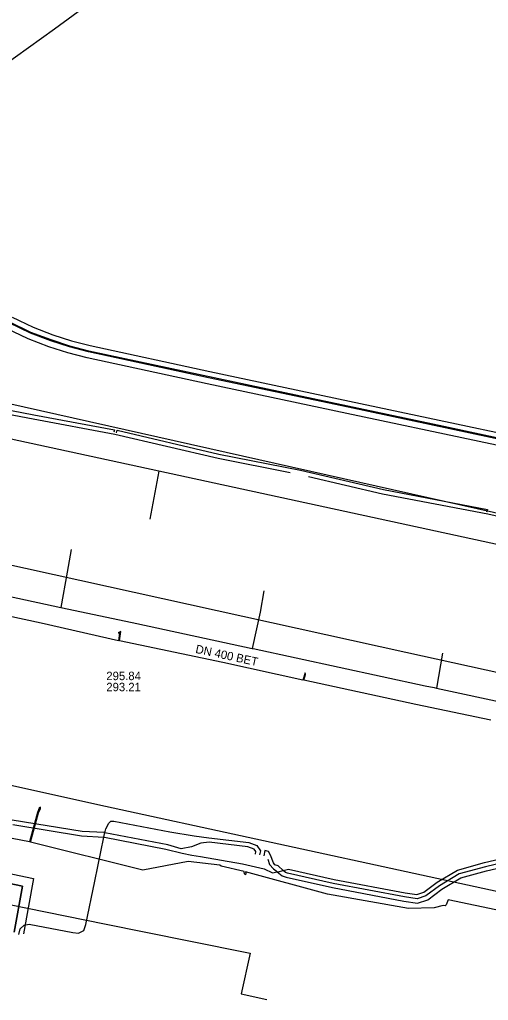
# Model space of a CAD drawing. Extents: x -598233 to -596890, y -1157848 to -1156431.
# Drawn here: x -597143.3 to -597098.9, y -1156713.1 to -1156620.3 of the extents above; entities that cross this region are included whole.
import ezdxf

# ---------------------------------------------------------------- set-up
doc = ezdxf.new("R2010")
doc.units = 0
for name, color, linetype in [('Vrstva 12', 7, 'Continuous'), ('Vrstva 13', 7, 'Continuous'), ('Vrstva 19', 7, 'Continuous'), ('Vrstva 25', 7, 'Continuous'), ('Vrstva 26', 7, 'Continuous'), ('Vrstva 37', 7, 'Continuous'), ('Vrstva 38', 7, 'Continuous'), ('Vrstva 42', 7, 'Continuous'), ('Vrstva 55', 7, 'Continuous'), ('Vrstva 9', 7, 'Continuous')]:
    doc.layers.add(name, color=color, linetype=linetype)

msp = doc.modelspace()

# ---------------------------------------------------------------- linework, layer by layer
at = {"layer": 'Vrstva 12'}
for points in [[(-597002.27, -1156687.69), (-597020.83, -1156683.69), (-597091.98, -1156668.39), (-597150.87, -1156655.17)], [(-597149.84, -1156702.93), (-597135.23, -1156705.9), (-597127.25, -1156707.5)], [(-597127.25, -1156707.5), (-597121.47, -1156708.66), (-597122.31, -1156712.53), (-597119.87, -1156713.06)]]:
    msp.add_lwpolyline(points, dxfattribs=at)
at = {"layer": 'Vrstva 13'}
for points in [[(-597144.89, -1156624.69), (-597139.98, -1156621.16), (-597135.15, -1156617.58)], [(-597084.22, -1156685.17), (-597106.726, -1156680.198), (-597165.716, -1156667.167), (-597175.517, -1156665.001)]]:
    msp.add_lwpolyline(points, dxfattribs=at)
at = {"layer": 'Vrstva 19'}
msp.add_lwpolyline([(-597153.74, -1156690.63), (-597135.86, -1156694.59), (-597088.849, -1156704.811), (-597082.78, -1156706.13), (-597053.385, -1156713.142)], dxfattribs=at)
at = {"layer": 'Vrstva 25'}
msp.add_lwpolyline([(-597087.165, -1156662.298), (-597112.173, -1156656.978), (-597125.389, -1156654.183), (-597136.739, -1156651.732), (-597138.536, -1156651.265), (-597140.312, -1156650.68), (-597142.231, -1156649.963), (-597144.243, -1156648.998)], dxfattribs=at)
at = {"layer": 'Vrstva 26'}
for points in [[(-597143.971, -1156648.463), (-597141.996, -1156649.41), (-597140.113, -1156650.114), (-597138.367, -1156650.689), (-597136.601, -1156651.148), (-597125.264, -1156653.596), (-597112.049, -1156656.391), (-597087.039, -1156661.711)], [(-597087.29, -1156662.885), (-597112.298, -1156657.564), (-597125.515, -1156654.769), (-597136.878, -1156652.315), (-597138.706, -1156651.841), (-597140.511, -1156651.246), (-597142.466, -1156650.515), (-597144.515, -1156649.533)]]:
    msp.add_lwpolyline(points, dxfattribs=at)
at = {"layer": 'Vrstva 37'}
for p, q in [((-597130.1, -1156663.037), (-597130.94, -1156667.563)), ((-597089.088, -1156671.932), (-597130.1, -1156663.037))]:
    msp.add_line(p, q, dxfattribs=at)
for points in [[(-597130.1, -1156663.037), (-597160.394, -1156656.466), (-597160.772, -1156658.504), (-597163.161, -1156657.986)], [(-597179.006, -1156694.768), (-597142.983, -1156702.318), (-597143.773, -1156706.674)], [(-597143.773, -1156706.674), (-597142.983, -1156702.318), (-597179.003, -1156694.755)]]:
    msp.add_lwpolyline(points, dxfattribs=at)
at = {"layer": 'Vrstva 38'}
msp.add_lwpolyline([(-597177.936, -1156694.073), (-597141.941, -1156701.617), (-597142.887, -1156706.835)], dxfattribs=at)
at = {"layer": 'Vrstva 42'}
for points in [[(-597096.4, -1156660.25), (-597103.15, -1156658.82), (-597112.23, -1156656.88), (-597121.46, -1156654.93), (-597130.78, -1156652.94), (-597136.72, -1156651.66), (-597138.51, -1156651.19), (-597140.28, -1156650.61), (-597142.2, -1156649.89), (-597144.2, -1156648.93)], [(-597151.872, -1156655.786), (-597141.913, -1156657.693), (-597134.293, -1156659.105), (-597134.345, -1156659.335)], [(-597150.965, -1156656.366), (-597141.987, -1156658.087), (-597134.273, -1156659.516), (-597124.492, -1156661.816), (-597117.665, -1156663.161)], [(-597134.103, -1156659.395), (-597134.044, -1156659.158), (-597124.408, -1156661.424), (-597116.69, -1156662.946), (-597108.838, -1156664.774), (-597099.02, -1156666.66), (-597099.084, -1156666.919)], [(-597115.929, -1156663.534), (-597108.922, -1156665.166), (-597098.978, -1156667.074), (-597089.592, -1156669.196), (-597082.391, -1156670.668)], [(-597143.77, -1156706.67), (-597142.98, -1156702.32), (-597179, -1156694.75)], [(-597120.964, -1156699.295), (-597120.911, -1156699.057), (-597121.085, -1156698.82), (-597121.668, -1156698.593), (-597125.322, -1156698.165), (-597126.11, -1156698.241), (-597127.015, -1156698.599), (-597127.979, -1156698.778), (-597129.23, -1156698.4), (-597135.204, -1156697.268), (-597135.257, -1156697.258), (-597137.354, -1156697.145), (-597143.964, -1156696.072)], [(-597143.915, -1156696.486), (-597137.408, -1156697.549), (-597135.295, -1156697.689), (-597135.235, -1156697.693), (-597129.43, -1156698.83), (-597127.904, -1156699.208), (-597126.966, -1156699.377), (-597126.163, -1156699.519), (-597122.175, -1156700.216), (-597120.129, -1156700.677), (-597119.353, -1156701.077), (-597118.89, -1156700.98), (-597118.82, -1156700.965), (-597118.34, -1156700.841), (-597117.834, -1156700.711), (-597113.51, -1156701.682), (-597106.781, -1156702.955), (-597105.705, -1156703.109), (-597105.03, -1156702.892), (-597103.761, -1156701.958), (-597101.855, -1156700.804), (-597099.301, -1156700.102), (-597096.736, -1156699.495)], [(-597143.338, -1156706.891), (-597143.199, -1156706.354), (-597142.822, -1156706.014), (-597142.358, -1156705.915), (-597138.223, -1156706.725), (-597137.702, -1156706.775), (-597137.206, -1156706.522), (-597136.987, -1156705.962), (-597136.16, -1156701.868), (-597135.295, -1156697.689), (-597135.228, -1156697.365), (-597135.204, -1156697.268), (-597135.11, -1156696.886), (-597134.841, -1156696.353), (-597134.641, -1156696.164), (-597134.346, -1156696.16), (-597129.043, -1156697.196), (-597126.768, -1156697.568), (-597125.355, -1156697.753), (-597121.57, -1156698.201), (-597120.831, -1156698.49), (-597120.481, -1156698.969), (-597120.573, -1156699.372)], [(-597096.708, -1156699.9), (-597099.202, -1156700.49), (-597101.695, -1156701.175), (-597103.538, -1156702.291), (-597104.845, -1156703.253), (-597105.67, -1156703.518), (-597106.846, -1156703.35), (-597113.591, -1156702.074), (-597117.935, -1156701.098), (-597118.126, -1156701.041), (-597118.34, -1156700.841), (-597118.81, -1156700.402), (-597119.135, -1156700.307), (-597119.255, -1156700.129), (-597119.518, -1156699.379), (-597119.715, -1156699.044), (-597120.067, -1156698.966), (-597120.165, -1156699.454)], [(-597119.794, -1156699.768), (-597119.624, -1156700.285), (-597119.244, -1156700.692), (-597118.996, -1156700.889), (-597118.89, -1156700.98), (-597118.444, -1156701.363), (-597118.036, -1156701.485), (-597113.672, -1156702.466), (-597106.911, -1156703.745), (-597105.635, -1156703.927), (-597104.66, -1156703.614), (-597103.315, -1156702.624), (-597101.535, -1156701.546), (-597099.103, -1156700.878), (-597096.68, -1156700.305)]]:
    msp.add_lwpolyline(points, dxfattribs=at)
at = {"layer": 'Vrstva 55'}
for points in [[(-597098.689, -1156686.62), (-597105.78, -1156685.13), (-597116.381, -1156682.831), (-597116.21, -1156682.298), (-597116.26, -1156682.14), (-597116.479, -1156682.809), (-597124.05, -1156681.15), (-597133.821, -1156679.11), (-597133.699, -1156678.204), (-597133.95, -1156678.35), (-597133.821, -1156678.356), (-597133.919, -1156679.089), (-597141.23, -1156677.42), (-597151.34, -1156675.241), (-597151.32, -1156674.652), (-597151.42, -1156674.648), (-597151.44, -1156675.219), (-597159.95, -1156673.41), (-597170.87, -1156670.82), (-597171.4, -1156670.38), (-597171.532, -1156669.634), (-597171.857, -1156669.49)], [(-597097.61, -1156704.69), (-597102.72, -1156703.61), (-597102.93, -1156704.09), (-597103.021, -1156704.18), (-597103.204, -1156704.156), (-597104.04, -1156704.37), (-597106.47, -1156704.43), (-597114.15, -1156703.1), (-597121.887, -1156700.977), (-597121.866, -1156701.13), (-597121.91, -1156701.25), (-597121.985, -1156701.146), (-597122.013, -1156700.946), (-597124.21, -1156700.44), (-597124.32, -1156700.35), (-597127.31, -1156699.98), (-597131.62, -1156700.81), (-597142.222, -1156698.155), (-597141.473, -1156695.39), (-597141.294, -1156694.986), (-597141.3, -1156694.85), (-597141.404, -1156694.937), (-597141.587, -1156695.35), (-597142.339, -1156698.129), (-597154.33, -1156695.84)]]:
    msp.add_lwpolyline(points, dxfattribs=at)
at = {"layer": 'Vrstva 9'}
for p, q in [((-597138.375, -1156670.444), (-597138.765, -1156672.584)), ((-597138.765, -1156672.584), (-597139.354, -1156675.933)), ((-597120.161, -1156674.375), (-597120.515, -1156676.396)), ((-597120.515, -1156676.396), (-597121.272, -1156679.809)), ((-597103.255, -1156680.262), (-597103.82, -1156683.58))]:
    msp.add_line(p, q, dxfattribs=at)
for points in [[(-597166.776, -1156670.012), (-597157.115, -1156672.085), (-597139.354, -1156675.933), (-597136.227, -1156676.603), (-597132.189, -1156677.468)], [(-597132.189, -1156677.468), (-597121.272, -1156679.809), (-597121.181, -1156679.829), (-597104.895, -1156683.348), (-597104.056, -1156683.529), (-597103.82, -1156683.58), (-597096.921, -1156685.069), (-597093.304, -1156685.85)]]:
    msp.add_lwpolyline(points, dxfattribs=at)

# ---------------------------------------------------------------- texts
at = {"layer": 'Vrstva 12'}
msp.add_text('DN 400 BET', height=0.8, rotation=347.84268, dxfattribs=at).set_placement((-597126.681, -1156680.232))
for s, p in [('295.84', (-597135.065, -1156682.82)), ('293.21', (-597135.065, -1156683.87))]:
    msp.add_text(s, height=0.8, dxfattribs=at).set_placement(p)

doc.saveas('drawing.dxf')
